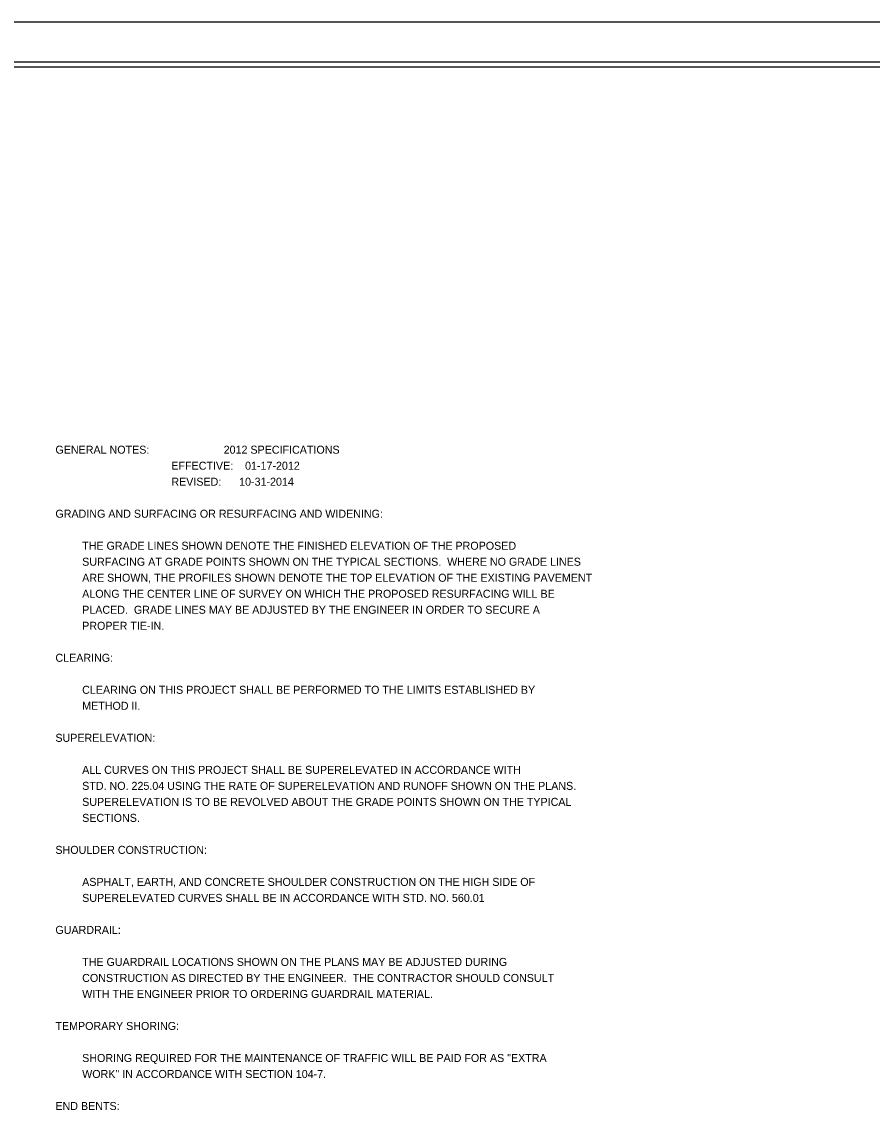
# Model space of a CAD drawing. Extents: x 1974126 to 1975810, y 438878 to 442173.
# Drawn here: x 1974833 to 1975258, y 441624 to 442173 of the extents above; entities that cross this region are included whole.
import ezdxf

# ---------------------------------------------------------------- set-up
doc = ezdxf.new("R2010")
doc.units = 0
for name, color, linetype in [('Default', 7, 'Continuous'), ('Sheet Cutting Line CELL', 7, 'Continuous'), ('Sheet Plan CELL', 7, 'Continuous'), ('Sheet Plot Border Inside CELL', 7, 'Continuous'), ('Sheet Plot Border Outside CELL', 7, 'Continuous')]:
    doc.layers.add(name, color=color, linetype=linetype)

msp = doc.modelspace()

# ---------------------------------------------------------------- linework, layer by layer
at = {"layer": 'Sheet Cutting Line CELL'}
msp.add_line((1975809.14, 442173.29), (1974125.64, 442173.29), dxfattribs=at)
at = {"layer": 'Sheet Plan CELL'}
msp.add_lwpolyline([(1975792.14, 442150.79), (1974292.14, 442150.79), (1974292.14, 441100.79), (1975792.14, 441100.79)], close=True, dxfattribs=at)
at = {"layer": 'Sheet Plot Border Inside CELL'}
msp.add_lwpolyline([(1974138.64, 441098.29), (1975804.64, 441098.29), (1975804.64, 442153.29), (1974138.64, 442153.29)], close=True, dxfattribs=at)
at = {"layer": 'Sheet Plot Border Outside CELL'}
msp.add_lwpolyline([(1974125.64, 441078.29), (1975809.14, 441078.29), (1975809.14, 442173.29), (1974125.64, 442173.29)], close=True, dxfattribs=at)

# ---------------------------------------------------------------- texts
at = {"layer": 'Default'}
for s, p in [('GENERAL NOTES:                         2012 SPECIFICATIONS', (1974849.54, 441957.54)), ('                                       EFFECTIVE:    01-17-2012', (1974849.54, 441949.54)), ('                                       REVISED:      10-31-2014', (1974849.54, 441941.54)), ('GRADING AND SURFACING OR RESURFACING AND WIDENING:  ', (1974849.54, 441925.54)), ('         THE GRADE LINES SHOWN DENOTE THE FINISHED ELEVATION OF THE PROPOSED ', (1974849.54, 441909.54)), ('         SURFACING AT GRADE POINTS SHOWN ON THE TYPICAL SECTIONS.  WHERE NO GRADE LINES ', (1974849.54, 441901.54)), ('         ARE SHOWN, THE PROFILES SHOWN DENOTE THE TOP ELEVATION OF THE EXISTING PAVEMENT ', (1974849.54, 441893.54)), ('         ALONG THE CENTER LINE OF SURVEY ON WHICH THE PROPOSED RESURFACING WILL BE ', (1974849.54, 441885.54)), ('         PLACED.  GRADE LINES MAY BE ADJUSTED BY THE ENGINEER IN ORDER TO SECURE A ', (1974849.54, 441877.54)), ('         PROPER TIE-IN.  ', (1974849.54, 441869.54)), ('CLEARING:  ', (1974849.54, 441853.54)), ('         CLEARING ON THIS PROJECT SHALL BE PERFORMED TO THE LIMITS ESTABLISHED BY ', (1974849.54, 441837.54)), ('         METHOD II.', (1974849.54, 441829.54)), ('SUPERELEVATION:  ', (1974849.54, 441813.54)), ('         ALL CURVES ON THIS PROJECT SHALL BE SUPERELEVATED IN ACCORDANCE WITH', (1974849.54, 441797.54)), ('         STD. NO. 225.04 USING THE RATE OF SUPERELEVATION AND RUNOFF SHOWN ON THE PLANS.', (1974849.54, 441789.54)), ('         SUPERELEVATION IS TO BE REVOLVED ABOUT THE GRADE POINTS SHOWN ON THE TYPICAL ', (1974849.54, 441781.54)), ('         SECTIONS.  ', (1974849.54, 441773.54)), ('SHOULDER CONSTRUCTION:  ', (1974849.54, 441757.54)), ('         ASPHALT, EARTH, AND CONCRETE SHOULDER CONSTRUCTION ON THE HIGH SIDE OF', (1974849.54, 441741.54)), ('         SUPERELEVATED CURVES SHALL BE IN ACCORDANCE WITH STD. NO. 560.01', (1974849.54, 441733.54)), ('GUARDRAIL:  ', (1974849.54, 441717.54)), ('         THE GUARDRAIL LOCATIONS SHOWN ON THE PLANS MAY BE ADJUSTED DURING ', (1974849.54, 441701.54)), ('         CONSTRUCTION AS DIRECTED BY THE ENGINEER.  THE CONTRACTOR SHOULD CONSULT', (1974849.54, 441693.54)), ('         WITH THE ENGINEER PRIOR TO ORDERING GUARDRAIL MATERIAL.', (1974849.54, 441685.54)), ('TEMPORARY SHORING:  ', (1974849.54, 441669.54)), ('         SHORING REQUIRED FOR THE MAINTENANCE OF TRAFFIC WILL BE PAID FOR AS "EXTRA ', (1974849.54, 441653.54)), ('         WORK" IN ACCORDANCE WITH SECTION 104-7.  ', (1974849.54, 441645.54)), ('END BENTS:  ', (1974849.54, 441629.54))]:
    msp.add_text(s, height=4, dxfattribs=at).set_placement(p)

doc.saveas('drawing.dxf')
